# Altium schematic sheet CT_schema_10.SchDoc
size 274 x 160 mm
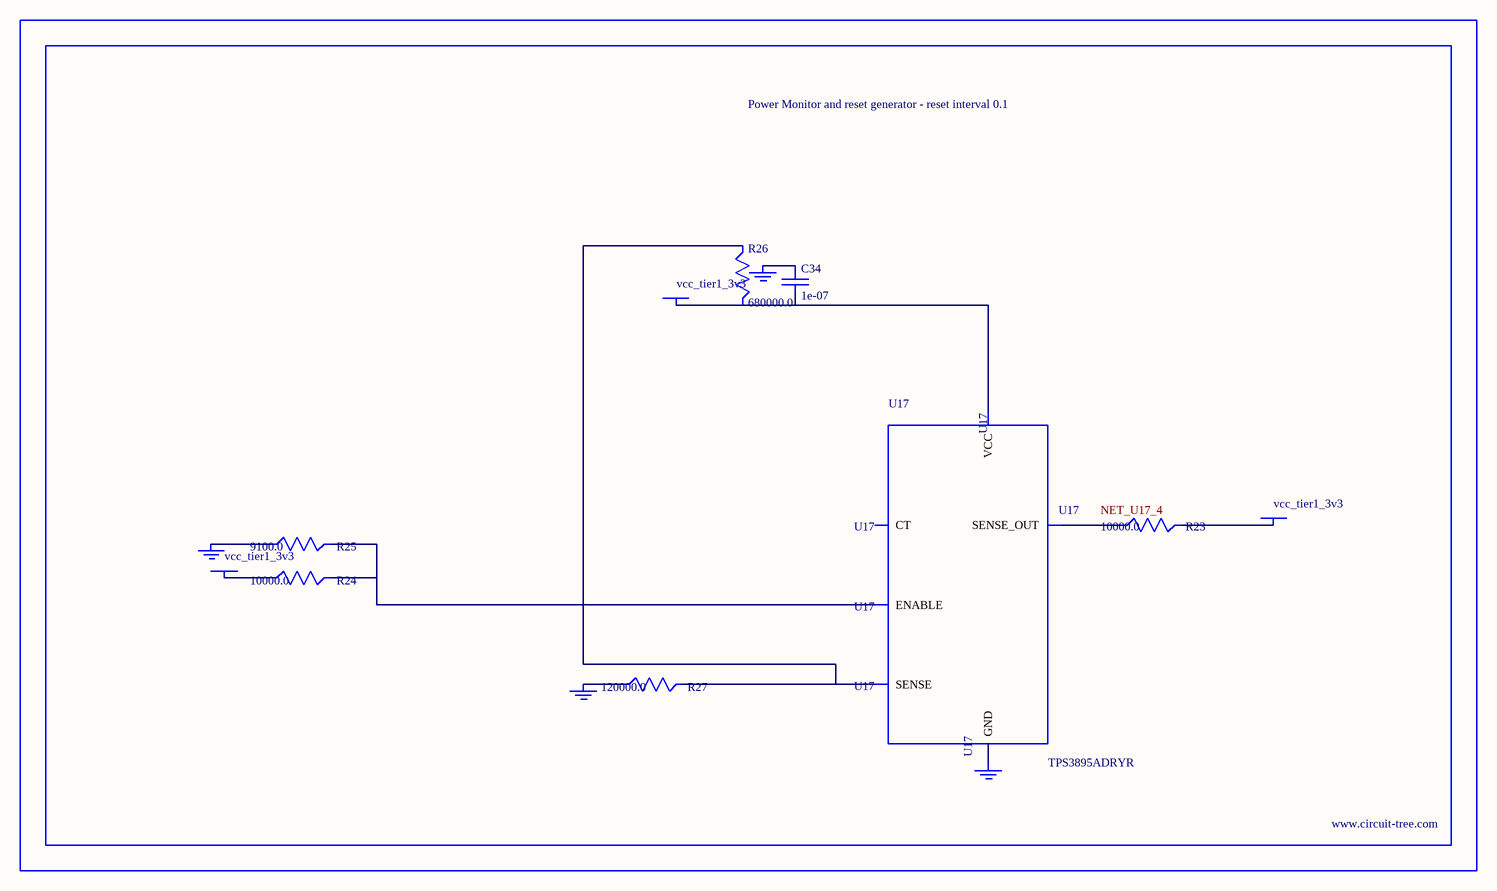
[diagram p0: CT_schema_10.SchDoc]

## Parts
BORDER9  (no value)
C34  1e-07  [C0402]
GND_INSTANCE_9_0  (no value)
GND_INSTANCE_9_1  (no value)
GND_INSTANCE_9_2  (no value)
GND_INSTANCE_9_3  (no value)
POWER_INSTANCE_9_0  vcc_tier1_3v3
POWER_INSTANCE_9_1  vcc_tier1_3v3
POWER_INSTANCE_9_2  vcc_tier1_3v3
R23  10000.0  [R0603]
R24  10000.0  [R0603]
R25  9100.0  [R0603]
R26  680000.0  [R0603]
R27  120000.0  [R0603]
U17  TPS3895ADRYR  [SON-6]

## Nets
NetC34_1: C34.1 GND_INSTANCE_9_2.0(GND)
NetC34_2: C34.2 POWER_INSTANCE_9_2.0(PWR) R26.2 U17.6(VCC)
NetGND_INSTANCE_9_0_0: GND_INSTANCE_9_0.0(GND) R25.1
NetGND_INSTANCE_9_1_0: GND_INSTANCE_9_1.0(GND) R27.1
NetGND_INSTANCE_9_3_0: GND_INSTANCE_9_3.0(GND) U17.2(GND)
NetPOWER_INSTANCE_9_0_0: POWER_INSTANCE_9_0.0(PWR) R24.1
NetPOWER_INSTANCE_9_1_0: POWER_INSTANCE_9_1.0(PWR) R23.2
NetR23_1: R23.1 U17.4(SENSE_OUT)
NetR24_2: R24.2 R25.2 U17.1(ENABLE)
NetR26_1: R26.1 R27.2 U17.3(SENSE)

Not connected (* = marked no-connect by the designer): U17 5(CT)

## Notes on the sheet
- Labels drawn without touching a wire or pin: NET_U17_4

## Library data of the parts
BORDER9 = BORDER_PAGE9
C34 = C0402C104K3RACTU
GND_INSTANCE_9_0-GND_INSTANCE_9_3 = GND
POWER_INSTANCE_9_0-POWER_INSTANCE_9_2 = PWR
R23 R24 = RC0603JR-0710KL
R25 = RC0603JR-079K1L
R26 = RC0603JR-07680KL
R27 = RC0603JR-07120KL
